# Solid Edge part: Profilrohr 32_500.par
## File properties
Username: ahadarics
Dokumentum tartalom típus: 0
Author: ahadarics
Last saved by: ahadarics
Revision: 89
Sűrűség: 0,000 kg/m^3
Pontosság: 0,990
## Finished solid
Body 1: solid body, 179 faces, 531 edges, 354 vertices.
  Faces by surface: cylinder 109, plane 70
  Edges by curve: line 313, circle 218
Bounding box of the edges (mm): 44.254 x 44.254 x 541.000, from (-22.1268, -22.1268, -13) to (22.1268, 22.1268, 528).
Cylindrical faces by radius (mm): R0.1 x16, R0.2 x30, R0.5 x32, R1 x6, R2.7 x8, R4.5 x4, R4.7 x4, R16 x1, R18 x8
Planar faces by outward normal: +x 6, +y 6, +z 1, -x 4, -y 4, -z 1, oblique 48
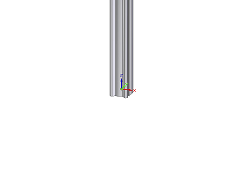
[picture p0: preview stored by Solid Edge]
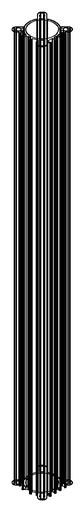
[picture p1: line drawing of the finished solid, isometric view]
